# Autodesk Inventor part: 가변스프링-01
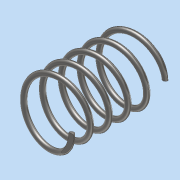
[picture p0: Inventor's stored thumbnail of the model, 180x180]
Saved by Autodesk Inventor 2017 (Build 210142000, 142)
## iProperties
Part Number: 가변스프링-01
Material: 강철, 연강
Document SubType Name: Modeling
Designer: MRC
Density: 7.85 g/cm^3
Appearance: 반연마
Mass: 8.42324 g
Surface Area: 21.7217 cm^2
Volume: 1.07302 cm^3
Author: MRC
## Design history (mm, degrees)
sketch "스케치1"
  geometry: L1 (0, 0)-(11, 0); L2 (11, 0)-(11, 36.411); L3 (11, 36.411)-(0, 36.411); L4 (0, 36.411)-(0, 0); C1 r 1 at (11, 0)
  constraints: 8 end point, 2 parallel, 1 centre point, 1 coincident, 1 horizontal, 1 perpendicular
  dimensions: "d0" = 36.4112 distance of L3.end L1.start (derived); "d1" = 22 diameter of L2 L4; "d2" = 2 diameter of C1
feature "코일1" sketch "스케치1" pitch "d3" = 10; turns "d5" = 5; dims "d4" = 36.4112 (= d0), "d6" = 0, angle "d7" = 90 deg, angle "d8" = 90 deg, "d9" = 0, "d10" = 0
sketch "스케치2"
  geometry: L1 (36.411, 17.383)-(0, 17.383); L2 (0, 17.383)-(0, -17.383); L3 (0, -17.383)-(36.411, -17.383); L4 (36.411, -17.383)-(36.411, 17.383); 2 further points
  constraints: 8 end point, 2 parallel, 1 coincident, 1 horizontal, 1 midpoint, 1 perpendicular
  dimensions: "d11" = 36.4112 distance of L2.end L3.end (= d0); "d12" = 34.76604 distance of L3.end L1.start
extrude "돌출1" sketch "스케치2" stored distance "d13" = 47.75; taper "d14" = 0 deg
node "솔리드1"
